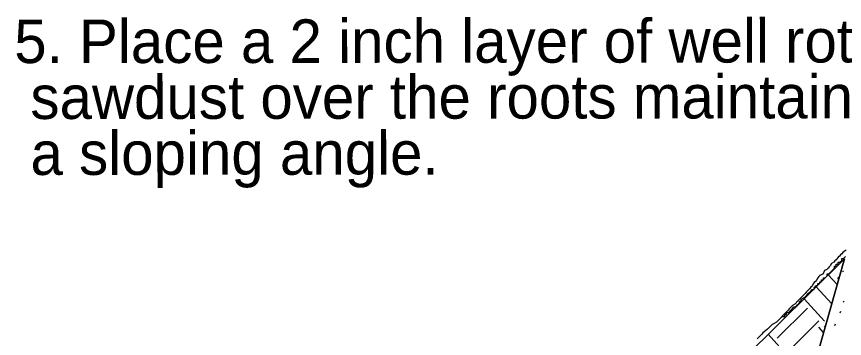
# Model space of a CAD drawing. Extents: x 816132 to 817815, y 885694 to 886789.
# Drawn here: x 816287.6 to 816415, y 885947 to 885996.6 of the extents above; entities that cross this region are included whole.
import ezdxf

# ---------------------------------------------------------------- set-up
doc = ezdxf.new("R2010")
doc.units = 0
doc.layers.add('Silt Fence Coir Fiber Wattle Break Detail CELL', color=7, linetype='Continuous')

msp = doc.modelspace()

# ---------------------------------------------------------------- linework, layer by layer
at = {"layer": 'Silt Fence Coir Fiber Wattle Break Detail CELL'}
for p, q in [((816369.08, 885913.8), (816415.02, 885959.28)), ((816415.02, 885959.28), (816405.14, 885924.17)), ((816405.14, 885924.17), (816415.02, 885959.28)), ((816414.7, 885957.45), (816414.81, 885957.29)), ((816413.9, 885955.3), (816412.53, 885956.82)), ((816413.94, 885956.23), (816414.25, 885956.54)), ((816413.06, 885952.33), (816410.67, 885954.98)), ((816411.95, 885949.65), (816408.81, 885953.14)), ((816414.8, 885952.75), (816414.91, 885952.59)), ((816404.68, 885947.06), (816409.33, 885951.66)), ((816414.38, 885950.98), (816414.48, 885951.23)), ((816406.44, 885945.11), (816411.08, 885949.71)), ((816411.82, 885947.91), (816411.06, 885948.76)), ((816411.93, 885948.77), (816412.12, 885948.96)), ((816413.55, 885949.02), (816413.66, 885949.27)), ((816406.41, 885944.16), (816403.27, 885947.65))]:
    msp.add_line(p, q, dxfattribs=at)
for points in [[(816415.31, 885960.62), (816414.96, 885960.43), (816414.78, 885960.25), (816414.61, 885960.06), (816414.43, 885959.88), (816414.26, 885959.69), (816414.08, 885959.51), (816413.9, 885959.32), (816413.73, 885959.14), (816413.55, 885958.95), (816413.38, 885958.77), (816413.02, 885958.58), (816412.85, 885958.21), (816412.67, 885958.03), (816412.5, 885957.85), (816412.32, 885957.66), (816411.97, 885957.48), (816411.79, 885957.1), (816411.62, 885956.92), (816411.26, 885956.73), (816411.09, 885956.55), (816410.91, 885956.37), (816410.74, 885956), (816410.56, 885955.81), (816410.38, 885955.63), (816410.21, 885955.44), (816410.03, 885955.07), (816409.86, 885954.89), (816409.68, 885954.7), (816409.51, 885954.52), (816409.33, 885954.33), (816409.15, 885954.15), (816408.98, 885953.96), (816408.8, 885953.78), (816408.63, 885953.59), (816408.45, 885953.41), (816408.28, 885953.22), (816408.1, 885953.04), (816407.92, 885952.85)], [(816405.54, 885950.39), (816405.83, 885950.39), (816405.83, 885950.69), (816406.11, 885950.69), (816406.11, 885950.99), (816406.4, 885950.99), (816406.68, 885951.29), (816406.96, 885951.59), (816407.25, 885951.88), (816407.53, 885951.88), (816407.81, 885952.18), (816408.1, 885952.48), (816408.1, 885952.78), (816408.38, 885952.78), (816408.38, 885953.08), (816408.95, 885953.37), (816409.23, 885953.67), (816409.51, 885953.97), (816409.8, 885954.27), (816410.08, 885954.57), (816410.37, 885954.57), (816410.36, 885954.86), (816410.65, 885955.16), (816410.93, 885955.16), (816410.93, 885955.46), (816411.22, 885955.46), (816411.22, 885955.76), (816411.5, 885955.76), (816411.5, 885956.06), (816411.78, 885956.06), (816411.78, 885956.35), (816412.07, 885956.35), (816412.35, 885956.65), (816412.35, 885956.95), (816412.63, 885956.95), (816412.92, 885957.25), (816413.2, 885957.55), (816413.48, 885957.84), (816413.48, 885958.14), (816413.77, 885958.14), (816413.77, 885958.44), (816414.05, 885958.44), (816414.05, 885958.74), (816414.33, 885958.74), (816414.62, 885959.04), (816414.62, 885959.33), (816414.9, 885959.33), (816415.19, 885959.63)], [(816407.92, 885952.85), (816407.4, 885952.3), (816407.04, 885952.11), (816406.87, 885951.93), (816406.69, 885951.74), (816406.52, 885951.56), (816406.34, 885951.37), (816406.16, 885951.19), (816405.99, 885951), (816405.81, 885950.82), (816405.64, 885950.63), (816405.46, 885950.45), (816405.29, 885950.26), (816405.11, 885950.08), (816404.93, 885949.89), (816404.76, 885949.71), (816404.58, 885949.53), (816404.23, 885949.34), (816403.88, 885949.16), (816403.53, 885948.79), (816403.17, 885948.42), (816402.65, 885948.05), (816402.47, 885947.86), (816402.29, 885947.68), (816402.12, 885947.49), (816401.94, 885947.31), (816401.77, 885947.12), (816401.59, 885946.94)]]:
    msp.add_lwpolyline(points, dxfattribs=at)

# ---------------------------------------------------------------- texts
for s, p in [('5. Place a 2 inch layer of well rotted ', (816287.29, 885989.43)), (' sawdust over the roots maintaining ', (816287.29, 885980.82)), (' a sloping angle.', (816287.3, 885972.2))]:
    msp.add_text(s, height=6.7041, rotation=0.045, dxfattribs=at).set_placement(p)

doc.saveas('drawing.dxf')
